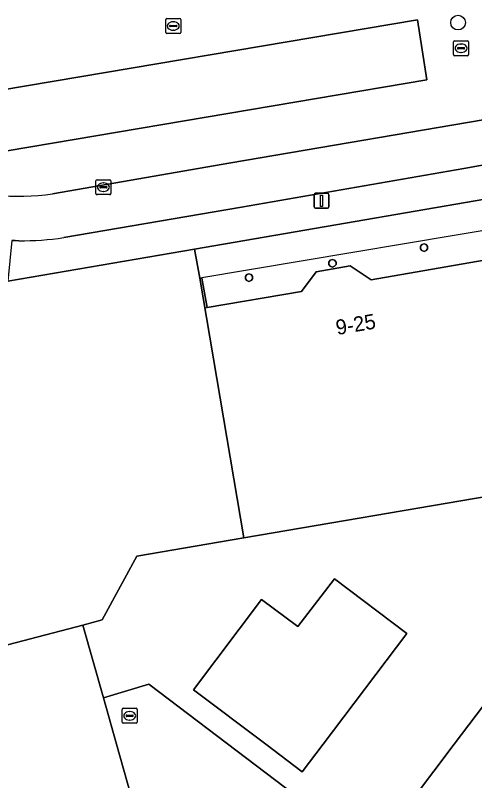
# Model space of a CAD drawing. Extents: x 161881 to 162523, y 381678 to 382381.
# Drawn here: x 161929.9 to 161960.5, y 382247.6 to 382298.6 of the extents above; entities that cross this region are included whole.
import ezdxf

# ---------------------------------------------------------------- set-up
doc = ezdxf.new("R2010")
doc.units = 0
for name, color, linetype in [('IMGEO_Boom', 7, 'Continuous'), ('IMGEO_Brandkraan', 7, 'Continuous'), ('IMGEO_Erf', 7, 'Continuous'), ('IMGEO_Fietspad_open', 7, 'Continuous'), ('IMGEO_Kolk', 7, 'Continuous'), ('IMGEO_Lichtmast', 7, 'Continuous'), ('IMGEO_Muur', 7, 'Continuous'), ('IMGEO_Pand', 7, 'Continuous'), ('IMGEO_Pand_nummerreeks', 7, 'Continuous'), ('IMGEO_Pand_overbouw', 7, 'Continuous'), ('IMGEO_Parkeervlak_open', 7, 'Continuous'), ('IMGEO_Rijbaan_lokaal_open', 7, 'Continuous'), ('IMGEO_Voetpad_open', 7, 'Continuous')]:
    doc.layers.add(name, color=color, linetype=linetype)

msp = doc.modelspace()

# ---------------------------------------------------------------- linework, layer by layer
at = {"layer": 'IMGEO_Boom'}
msp.add_circle((161959.405, 382298.149), 0.489, dxfattribs=at)
at = {"layer": 'IMGEO_Brandkraan'}
for p, q in [((161936.993, 382251.472), (161936.993, 382252.324)), ((161937.068, 382252.398), (161937.92, 382252.398)), ((161937.994, 382252.324), (161937.994, 382251.472)), ((161937.252, 382251.892), (161937.252, 382251.904)), ((161937.69, 382251.855), (161937.292, 382251.855)), ((161937.295, 382251.941), (161937.693, 382251.941)), ((161937.481, 382252.178), (161937.506, 382252.178)), ((161937.736, 382251.904), (161937.736, 382251.892)), ((161937.92, 382251.398), (161937.068, 382251.398)), ((161937.504, 382251.618), (161937.479, 382251.618))]:
    msp.add_line(p, q, dxfattribs=at)
for points in [[(161936.993, 382251.472), (161936.993, 382252.324)], [(161937.068, 382252.398), (161937.92, 382252.398)], [(161937.994, 382252.324), (161937.994, 382251.472)], [(161937.92, 382251.398), (161937.068, 382251.398)]]:
    msp.add_lwpolyline(points, dxfattribs=at)
for centre, radius, start, end in [((161937.07, 382252.322), 0.0765, 91.552, 178.448), ((161937.07, 382252.322), 0.0765, 91.552, 178.448), ((161937.918, 382252.322), 0.0765, 1.552, 88.448), ((161937.918, 382252.322), 0.0765, 1.552, 88.448), ((161937.292, 382251.901), 0.0403, 85.8775, 175.7526), ((161937.289, 382251.891), 0.0366, 178.938, 274.7102), ((161937.693, 382251.898), 0.043, 264.8664, 352.4533), ((161937.697, 382251.903), 0.0386, 1.7309, 96.639), ((161937.07, 382251.474), 0.0765, 181.552, 268.448), ((161937.07, 382251.474), 0.0765, 181.552, 268.448), ((161937.918, 382251.474), 0.0765, 271.552, 358.448), ((161937.918, 382251.474), 0.0765, 271.552, 358.448)]:
    msp.add_arc(centre, radius, start, end, dxfattribs=at)
for centre, major_axis, ratio, start_param, end_param in [((161937.48, 382251.898), (-0.387, 0.002), 0.722429, 4.712389, 7.853982), ((161937.505, 382251.898), (-0.39, 0.002), 0.717154, 1.570796, 4.712389)]:
    msp.add_ellipse(centre, major_axis=major_axis, ratio=ratio, start_param=start_param, end_param=end_param, dxfattribs=at)
at = {"layer": 'IMGEO_Erf'}
for points in [[(161990.561, 382247.065), (161986.69, 382250), (161976.285, 382257.889), (161975.098, 382256.278), (161961.553, 382266.566), (161945.111, 382263.77), (161937.98, 382262.557), (161935.649, 382258.303), (161934.37, 382257.936), (161935.75, 382253.101), (161938.776, 382254.005), (161949.183, 382246.105)], [(161953.642, 382242.72), (161959.141, 382250), (161964.528, 382257.096), (161973.351, 382250.518), (161972.961, 382250), (161962.44, 382236.041)]]:
    msp.add_lwpolyline(points, dxfattribs=at)
msp.add_lwpolyline([(161949.012, 382248.168), (161946.576, 382250), (161941.742, 382253.635), (161946.288, 382259.668), (161948.711, 382257.866), (161951.15, 382261.044), (161955.989, 382257.385), (161950.399, 382250)], close=True, dxfattribs=at)
at = {"layer": 'IMGEO_Fietspad_open'}
for points in [[(161963.045, 382292.008), (161944.233, 382288.786), (161932.344, 382286.729)], [(161933.095, 382283.812), (161944.946, 382285.84), (161959.789, 382288.411), (161964.711, 382289.303)], [(161929.624, 382283.615), (161929.861, 382283.61), (161930.098, 382283.601)]]:
    msp.add_lwpolyline(points, dxfattribs=at)
for centre, radius, start, end in [((161930.145, 382301.281), 14.717, 219.893, 278.5914), ((161930.428, 382300.31), 16.713, 268.8702, 279.1841)]:
    msp.add_arc(centre, radius, start, end, dxfattribs=at)
at = {"layer": 'IMGEO_Kolk'}
for p, q in [((161939.898, 382297.499), (161939.898, 382298.351)), ((161939.973, 382298.425), (161940.825, 382298.425)), ((161940.899, 382298.351), (161940.899, 382297.499)), ((161940.157, 382297.919), (161940.157, 382297.931)), ((161940.595, 382297.882), (161940.197, 382297.882)), ((161940.2, 382297.968), (161940.598, 382297.968)), ((161940.386, 382298.205), (161940.411, 382298.205)), ((161940.641, 382297.931), (161940.641, 382297.919)), ((161940.825, 382297.425), (161939.973, 382297.425)), ((161940.409, 382297.645), (161940.384, 382297.645)), ((161959.102, 382296.015), (161959.102, 382296.867)), ((161959.177, 382296.941), (161960.029, 382296.941)), ((161960.103, 382296.867), (161960.103, 382296.015)), ((161959.361, 382296.435), (161959.361, 382296.447)), ((161959.799, 382296.398), (161959.401, 382296.398)), ((161959.404, 382296.484), (161959.802, 382296.484)), ((161959.59, 382296.721), (161959.615, 382296.721)), ((161959.845, 382296.447), (161959.845, 382296.435)), ((161960.029, 382295.941), (161959.177, 382295.941)), ((161959.613, 382296.161), (161959.588, 382296.161)), ((161935.24, 382286.745), (161935.24, 382287.597)), ((161935.315, 382287.671), (161936.167, 382287.671)), ((161936.241, 382287.597), (161936.241, 382286.745)), ((161935.499, 382287.165), (161935.499, 382287.177)), ((161935.937, 382287.128), (161935.539, 382287.128)), ((161935.542, 382287.214), (161935.94, 382287.214)), ((161935.728, 382287.451), (161935.753, 382287.451)), ((161935.983, 382287.177), (161935.983, 382287.165)), ((161936.167, 382286.671), (161935.315, 382286.671)), ((161935.751, 382286.891), (161935.726, 382286.891))]:
    msp.add_line(p, q, dxfattribs=at)
for points in [[(161939.898, 382297.499), (161939.898, 382298.351)], [(161939.973, 382298.425), (161940.825, 382298.425)], [(161940.899, 382298.351), (161940.899, 382297.499)], [(161940.825, 382297.425), (161939.973, 382297.425)], [(161959.102, 382296.015), (161959.102, 382296.867)], [(161959.177, 382296.941), (161960.029, 382296.941)], [(161960.103, 382296.867), (161960.103, 382296.015)], [(161960.029, 382295.941), (161959.177, 382295.941)], [(161935.24, 382286.745), (161935.24, 382287.597)], [(161935.315, 382287.671), (161936.167, 382287.671)], [(161936.241, 382287.597), (161936.241, 382286.745)], [(161936.167, 382286.671), (161935.315, 382286.671)]]:
    msp.add_lwpolyline(points, dxfattribs=at)
for centre, radius, start, end in [((161939.975, 382298.349), 0.0765, 91.552, 178.448), ((161939.975, 382298.349), 0.0765, 91.552, 178.448), ((161940.823, 382298.349), 0.0765, 1.552, 88.448), ((161940.823, 382298.349), 0.0765, 1.552, 88.448), ((161940.197, 382297.928), 0.0403, 85.8775, 175.7526), ((161940.194, 382297.918), 0.0366, 178.938, 274.7102), ((161940.598, 382297.925), 0.043, 264.8664, 352.4533), ((161940.602, 382297.93), 0.0386, 1.7309, 96.639), ((161939.975, 382297.501), 0.0765, 181.552, 268.448), ((161939.975, 382297.501), 0.0765, 181.552, 268.448), ((161940.823, 382297.501), 0.0765, 271.552, 358.448), ((161940.823, 382297.501), 0.0765, 271.552, 358.448), ((161959.179, 382296.865), 0.0765, 91.552, 178.448), ((161959.179, 382296.865), 0.0765, 91.552, 178.448), ((161960.027, 382296.865), 0.0765, 1.552, 88.448), ((161960.027, 382296.865), 0.0765, 1.552, 88.448), ((161959.401, 382296.444), 0.0403, 85.8775, 175.7526), ((161959.398, 382296.434), 0.0366, 178.938, 274.7102), ((161959.802, 382296.441), 0.043, 264.8664, 352.4533), ((161959.806, 382296.446), 0.0386, 1.7309, 96.639), ((161959.179, 382296.017), 0.0765, 181.552, 268.448), ((161959.179, 382296.017), 0.0765, 181.552, 268.448), ((161960.027, 382296.017), 0.0765, 271.552, 358.448), ((161960.027, 382296.017), 0.0765, 271.552, 358.448), ((161935.317, 382287.595), 0.0765, 91.552, 178.448), ((161935.317, 382287.595), 0.0765, 91.552, 178.448), ((161936.165, 382287.595), 0.0765, 1.552, 88.448), ((161936.165, 382287.595), 0.0765, 1.552, 88.448), ((161935.539, 382287.174), 0.0403, 85.8775, 175.7526), ((161935.536, 382287.164), 0.0366, 178.938, 274.7102), ((161935.94, 382287.171), 0.043, 264.8664, 352.4533), ((161935.944, 382287.176), 0.0386, 1.7309, 96.639), ((161935.317, 382286.747), 0.0765, 181.552, 268.448), ((161935.317, 382286.747), 0.0765, 181.552, 268.448), ((161936.165, 382286.747), 0.0765, 271.552, 358.448), ((161936.165, 382286.747), 0.0765, 271.552, 358.448)]:
    msp.add_arc(centre, radius, start, end, dxfattribs=at)
for centre, major_axis, ratio, start_param, end_param in [((161940.385, 382297.925), (-0.387, 0.002), 0.722429, 4.712389, 7.853982), ((161940.41, 382297.925), (-0.39, 0.002), 0.717154, 1.570796, 4.712389), ((161959.589, 382296.441), (-0.387, 0.002), 0.722429, 4.712389, 7.853982), ((161959.614, 382296.441), (-0.39, 0.002), 0.717154, 1.570796, 4.712389), ((161935.727, 382287.171), (-0.387, 0.002), 0.722429, 4.712389, 7.853982), ((161935.752, 382287.171), (-0.39, 0.002), 0.717154, 1.570796, 4.712389)]:
    msp.add_ellipse(centre, major_axis=major_axis, ratio=ratio, start_param=start_param, end_param=end_param, dxfattribs=at)
at = {"layer": 'IMGEO_Lichtmast'}
for p, q in [((161949.795, 382285.864), (161949.795, 382286.664)), ((161949.795, 382286.664), (161949.795, 382285.864)), ((161949.895, 382286.764), (161950.685, 382286.764)), ((161950.685, 382286.764), (161949.895, 382286.764)), ((161950.785, 382286.664), (161950.785, 382285.864)), ((161950.785, 382285.864), (161950.785, 382286.664)), ((161950.685, 382285.764), (161949.895, 382285.764)), ((161949.895, 382285.764), (161950.685, 382285.764))]:
    msp.add_line(p, q, dxfattribs=at)
msp.add_lwpolyline([(161950.215, 382286.639), (161950.365, 382286.639), (161950.365, 382285.889), (161950.215, 382285.889), (161950.215, 382286.639)], dxfattribs=at)
for centre, start, end in [((161949.895, 382286.664), 90, 180), ((161949.895, 382286.664), 90, 180), ((161950.685, 382286.664), 0, 90), ((161950.685, 382286.664), 360, 90), ((161949.895, 382285.864), 180, 270), ((161949.895, 382285.864), 180, 270), ((161950.685, 382285.864), 270, 0), ((161950.685, 382285.864), 270, 0)]:
    msp.add_arc(centre, 0.1, start, end, dxfattribs=at)
at = {"layer": 'IMGEO_Muur'}
msp.add_lwpolyline([(161949.183, 382246.105), (161938.776, 382254.005), (161935.75, 382253.101)], dxfattribs=at)
at = {"layer": 'IMGEO_Pand'}
for points in [[(161945.111, 382263.77), (161942.166, 382281.089), (161941.807, 382283.041), (161929.352, 382280.894), (161927.087, 382276.882), (161922.385, 382268.556), (161920.099, 382264.507), (161922.313, 382256.656), (161923.36, 382256.961), (161923.866, 382255.207), (161934.37, 382257.936), (161935.649, 382258.303), (161937.98, 382262.557)], [(161957.133, 382282.888), (161957.28, 382282.936), (161957.371, 382283.061), (161957.371, 382283.215), (161957.28, 382283.34), (161957.133, 382283.388), (161956.986, 382283.34), (161956.895, 382283.215), (161956.895, 382283.061), (161956.986, 382282.936)], [(161961.553, 382266.566), (161965.332, 382282.123), (161963.192, 382282.647), (161953.601, 382280.995), (161952.204, 382281.916), (161949.93, 382281.52), (161948.949, 382280.212), (161942.66, 382279.14), (161942.312, 382281.106), (161942.166, 382281.089), (161945.111, 382263.77)], [(161951.022, 382281.842), (161951.169, 382281.89), (161951.26, 382282.015), (161951.26, 382282.169), (161951.169, 382282.294), (161951.022, 382282.342), (161950.875, 382282.294), (161950.784, 382282.169), (161950.784, 382282.015), (161950.875, 382281.89)], [(161945.453, 382280.888), (161945.6, 382280.936), (161945.691, 382281.061), (161945.691, 382281.215), (161945.6, 382281.34), (161945.453, 382281.388), (161945.306, 382281.34), (161945.215, 382281.215), (161945.215, 382281.061), (161945.306, 382280.936)], [(161949.012, 382248.168), (161950.399, 382250), (161955.989, 382257.385), (161951.15, 382261.044), (161948.711, 382257.866), (161946.288, 382259.668), (161941.742, 382253.635), (161946.576, 382250)], [(161936.623, 382250), (161935.75, 382253.101), (161934.37, 382257.936), (161923.866, 382255.207), (161922.804, 382254.896), (161924.171, 382250), (161936.116, 382207.222), (161932.713, 382206.28), (161938.437, 382185.838), (161950.119, 382189.128), (161948.081, 382196.398), (161947.6, 382198.115), (161945.279, 382206.396), (161951.594, 382208.165), (161950.728, 382211.253), (161947.763, 382210.422), (161946.508, 382214.887), (161945.701, 382217.756)], [(161953.642, 382242.72), (161962.44, 382236.041), (161972.961, 382250), (161973.351, 382250.518), (161964.528, 382257.096), (161959.141, 382250)]]:
    msp.add_lwpolyline(points, close=True, dxfattribs=at)
at = {"layer": 'IMGEO_Pand_overbouw'}
msp.add_lwpolyline([(161965.332, 382282.123), (161966.04, 382285.113), (161942.166, 382281.089), (161942.501, 382279.117), (161942.66, 382279.14), (161948.949, 382280.212), (161949.93, 382281.52), (161952.204, 382281.916), (161953.601, 382280.995), (161963.192, 382282.647)], close=True, dxfattribs=at)
at = {"layer": 'IMGEO_Parkeervlak_open'}
msp.add_lwpolyline([(161927.847, 382289.344), (161957.325, 382294.341), (161956.687, 382298.34), (161927.169, 382293.363)], close=True, dxfattribs=at)
at = {"layer": 'IMGEO_Rijbaan_lokaal_open'}
msp.add_lwpolyline([(161956.687, 382298.34), (161957.325, 382294.341), (161927.847, 382289.344), (161927.169, 382293.363)], close=True, dxfattribs=at)
msp.add_lwpolyline([(161932.344, 382286.729), (161944.233, 382288.786), (161963.045, 382292.008)], dxfattribs=at)
msp.add_arc((161930.145, 382301.281), 14.717, 219.893, 278.5914, dxfattribs=at)
at = {"layer": 'IMGEO_Voetpad_open'}
for points in [[(161964.711, 382289.303), (161959.789, 382288.411), (161944.946, 382285.84), (161933.095, 382283.812)], [(161941.807, 382283.041), (161966.622, 382287.308), (161986.642, 382272.1), (161991.25, 382268.628), (161996.729, 382264.459), (162000, 382261.97), (162001.181, 382261.071), (162005.558, 382257.74), (162008.206, 382255.54), (162011.059, 382253.58), (162015.722, 382250.073), (162015.794, 382250), (162016.53, 382249.251), (162016.754, 382249.024), (162018.527, 382250.66), (162010.479, 382256.829), (162002.346, 382262.989), (162000, 382264.77), (161990.844, 382271.72), (161969.897, 382287.586)], [(161930.098, 382283.601), (161929.861, 382283.61), (161929.624, 382283.615), (161929.352, 382280.894), (161941.807, 382283.041)]]:
    msp.add_lwpolyline(points, dxfattribs=at)
for points in [[(161966.622, 382287.308), (161941.807, 382283.041), (161942.166, 382281.089), (161942.312, 382281.106), (161942.66, 382279.14), (161948.949, 382280.212), (161949.93, 382281.52), (161952.204, 382281.916), (161953.601, 382280.995), (161963.192, 382282.647), (161965.332, 382282.123), (161967.512, 382281.59), (161975.292, 382275.656), (161976.922, 382275.895), (161978.749, 382274.496), (161979.047, 382272.85), (161984.121, 382269.036), (161985.32, 382270.611), (161985.45, 382270.523), (161986.642, 382272.1)], [(161956.986, 382282.936), (161956.895, 382283.061), (161956.895, 382283.215), (161956.986, 382283.34), (161957.133, 382283.388), (161957.28, 382283.34), (161957.371, 382283.215), (161957.371, 382283.061), (161957.28, 382282.936), (161957.133, 382282.888)], [(161950.875, 382281.89), (161950.784, 382282.015), (161950.784, 382282.169), (161950.875, 382282.294), (161951.022, 382282.342), (161951.169, 382282.294), (161951.26, 382282.169), (161951.26, 382282.015), (161951.169, 382281.89), (161951.022, 382281.842)], [(161945.691, 382281.061), (161945.6, 382280.936), (161945.453, 382280.888), (161945.306, 382280.936), (161945.215, 382281.061), (161945.215, 382281.215), (161945.306, 382281.34), (161945.453, 382281.388), (161945.6, 382281.34), (161945.691, 382281.215)], [(161935.75, 382253.101), (161936.623, 382250), (161945.701, 382217.756), (161948.484, 382218.502), (161945.674, 382228.115), (161951.907, 382223.307), (161952.337, 382223.947), (161945.479, 382229.234), (161941.155, 382244.658), (161943.42, 382245.308), (161944.841, 382240.436), (161949.183, 382246.105), (161938.776, 382254.005)]]:
    msp.add_lwpolyline(points, close=True, dxfattribs=at)
msp.add_arc((161930.428, 382300.31), 16.713, 268.8702, 279.1841, dxfattribs=at)

# ---------------------------------------------------------------- texts
at = {"layer": 'IMGEO_Pand_nummerreeks'}
msp.add_text('9-25', height=1, rotation=9.7394, dxfattribs=at).set_placement((161951.337, 382277.301))

doc.saveas('drawing.dxf')
